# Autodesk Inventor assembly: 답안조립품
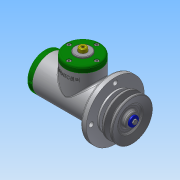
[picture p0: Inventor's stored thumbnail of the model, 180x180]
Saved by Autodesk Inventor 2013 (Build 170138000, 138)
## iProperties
Created: 2016-08
Part Number: 답안조립품
Document SubType Name: Assembly
Designer: Administrator
Author: Administrator
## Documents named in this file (25)
- C:\Users\Administrator\Desktop\460808V1004\답안조립품.iam
- C:\Users\Administrator\Desktop\460808V1004\본체.ipt
- C:\Users\Administrator\Desktop\460808V1004\사이드 커버.ipt
- 사이드 커버.ipt
- C:\Users\Administrator\Desktop\460808V1004\탑 커버.ipt
- 탑 커버.ipt
- C:\Users\Administrator\Desktop\460808V1004\탑 부시.ipt
- C:\Users\Administrator\Desktop\460808V1004\볼트 M4 x 12.ipt
- C:\Users\Administrator\Desktop\460808V1004\베어링 15 x 35 x 11.ipt
- C:\Users\Administrator\Desktop\460808V1004\편심축.ipt
- C:\Users\Administrator\Desktop\460808V1004\부시1.ipt
- C:\Users\Administrator\Desktop\460808V1004\멈춤링 35x1.6.ipt
- C:\Users\Administrator\Desktop\460808V1004\부시2.ipt
- C:\Users\Administrator\Desktop\460808V1004\와셔 10x21.ipt
- C:\Users\Administrator\Desktop\460808V1004\너트 M10.ipt
- C:\Users\Administrator\Desktop\460808V1004\멈춤링 15 x 1.ipt
- C:\Users\Administrator\Desktop\460808V1004\오일 실 15 25 7.ipt
- C:\Users\Administrator\Desktop\460808V1004\키 4 x 4 x 18.ipt
- C:\Users\Administrator\Desktop\460808V1004\V-벨트풀리.ipt
- C:\Users\Administrator\Desktop\460808V1004\와셔 4x16.ipt
- C:\Users\Administrator\Desktop\460808V1004\볼트 M4 x 10.ipt
- C:\Users\Administrator\Desktop\460808V1004\슬라이더.ipt
- C:\Users\Administrator\Desktop\460808V1004\링크.ipt
- C:\Users\Administrator\Desktop\460808V1004\클래스터 핀 6 x 24.ipt
- C:\Users\Administrator\Desktop\460808V1004\분할핀 1.6 x 12.ipt
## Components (6 placed, 3 different names)
1. V-벨트풀리:1 — 각도:3
2. ISO 4017 M4 x 10:1
3. ISO 4762 M4 x 12:1
4. ISO 4762 M4 x 12:2
5. ISO 4762 M4 x 12:3
6. ISO 4762 M4 x 12:4
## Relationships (1: Angle 1)
- 각도:3 [Angle]: V-벨트풀리:1
